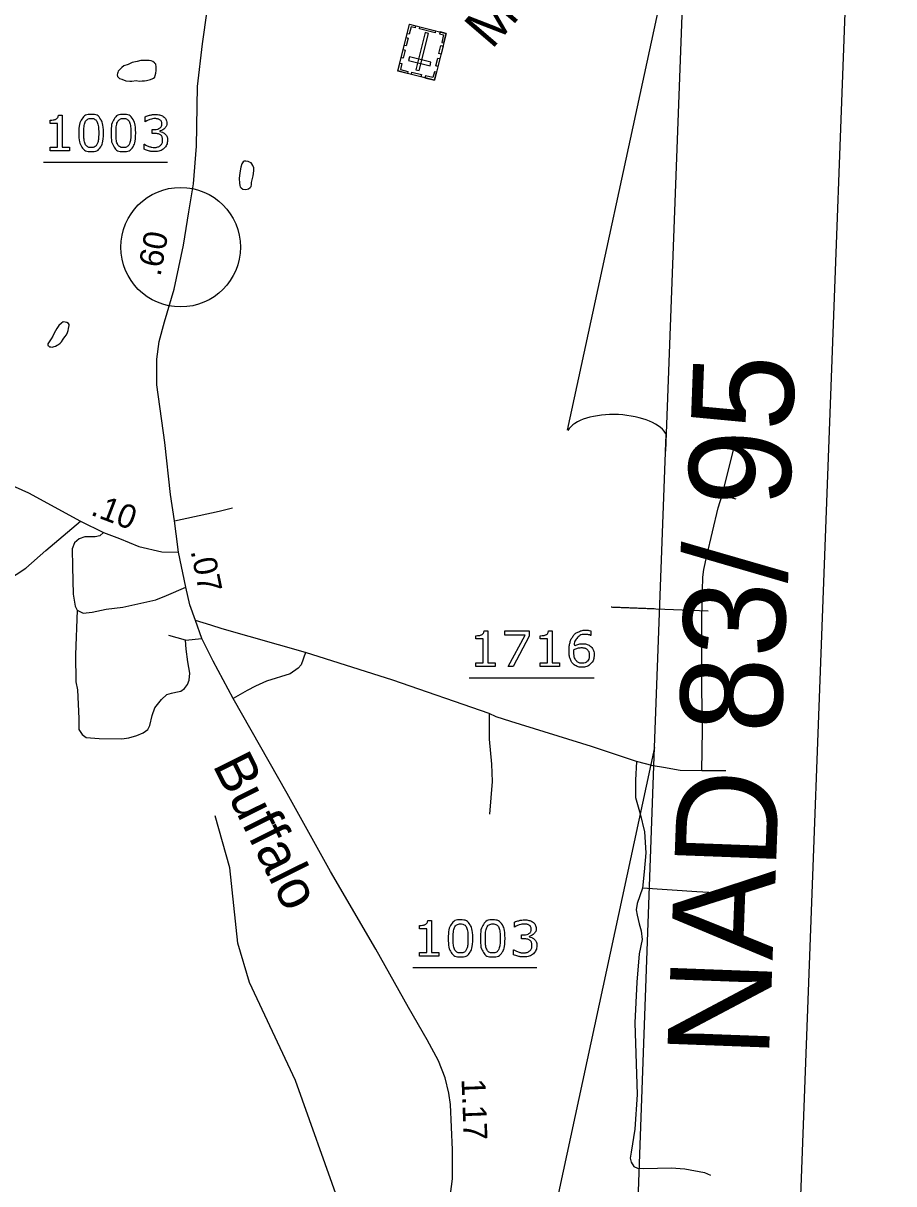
# Model space of a CAD drawing. Extents: x 2169602 to 2449496, y 721995 to 810662.
# Drawn here: x 2170470.8 to 2170579.9, y 724655.5 to 724801.1 of the extents above; entities that cross this region are included whole.
import ezdxf

# ---------------------------------------------------------------- set-up
doc = ezdxf.new("R2010")
doc.units = 0
for name, color, linetype in [('Old_Level_1', 7, 'Continuous'), ('Prop North Arrow NAD83 for Plan Sheets CELL', 7, 'Continuous'), ('Prop Shade Medium', 7, 'Continuous')]:
    doc.layers.add(name, color=color, linetype=linetype)

msp = doc.modelspace()

# ---------------------------------------------------------------- linework, layer by layer
at = {"layer": 'Old_Level_1'}
for p, q in [((2170473.29, 724783.7), (2170488.84, 724783.7)), ((2170558.41, 724741.94), (2170560.11, 724741.45)), ((2170491.09, 724723.76), (2170489, 724724.31)), ((2170491.09, 724723.76), (2170493.14, 724723.93)), ((2170526.66, 724719.02), (2170542.34, 724719.02)), ((2170519.6, 724682.67), (2170535.15, 724682.67))]:
    msp.add_line(p, q, dxfattribs=at)
for points in [[(2170008.61, 724987.87), (2170579.91, 724966.5), (2170563.13, 724517.9), (2169991.83, 724539.28)], [(2170522.32, 724793.99), (2170517.73, 724795.13), (2170519.19, 724801.01), (2170523.79, 724799.86)], [(2170519.96, 724800.82), (2170519.89, 724800.55), (2170519.39, 724800.68), (2170519.15, 724799.75), (2170518.9, 724799.81), (2170519.19, 724801.01)], [(2170519.98, 724795.29), (2170520.41, 724795.19), (2170521.57, 724799.86), (2170521.14, 724799.97)], [(2170522.39, 724799.93), (2170520.44, 724800.42), (2170520.5, 724800.68), (2170522.46, 724800.19)], [(2170523.02, 724800.05), (2170522.96, 724799.79), (2170523.46, 724799.66), (2170523.23, 724798.73), (2170523.49, 724798.66), (2170523.79, 724799.86)], [(2170519.04, 724799.27), (2170518.79, 724798.28), (2170518.53, 724798.34), (2170518.78, 724799.34)], [(2170518.66, 724797.75), (2170518.41, 724796.76), (2170518.15, 724796.82), (2170518.4, 724797.82)], [(2170521.77, 724795.79), (2170521.88, 724796.23), (2170519.17, 724796.9), (2170519.06, 724796.47)], [(2170523.39, 724798.25), (2170523.14, 724797.25), (2170522.87, 724797.32), (2170523.12, 724798.32)], [(2170517.98, 724796.13), (2170518.24, 724796.07), (2170518.06, 724795.33), (2170518.99, 724795.09), (2170518.93, 724794.84), (2170517.73, 724795.14)], [(2170523, 724796.7), (2170522.75, 724795.7), (2170522.49, 724795.77), (2170522.74, 724796.76)], [(2170520.62, 724794.42), (2170519.42, 724794.71), (2170519.49, 724794.98), (2170520.68, 724794.68)], [(2170522.57, 724794.99), (2170522.31, 724795.05), (2170522.13, 724794.31), (2170521.19, 724794.55), (2170521.13, 724794.29), (2170522.32, 724793.99)]]:
    msp.add_lwpolyline(points, close=True, dxfattribs=at)
for points in [[(2170490.24, 724734.77), (2170489.92, 724737.07), (2170489.72, 724738.72), (2170489.22, 724742.03), (2170488.49, 724748.52), (2170487.51, 724755.77), (2170487.51, 724758.97), (2170487.81, 724761.19), (2170488.45, 724763.67), (2170489.69, 724767.77), (2170490.84, 724773.27), (2170491.52, 724777.46), (2170492.12, 724781), (2170492.5, 724785.69), (2170492.59, 724793.21), (2170493.23, 724798.54), (2170493.83, 724802.68), (2170494.72, 724807.5), (2170495.36, 724811.52)], [(2170484.91, 724793.93), (2170485.29, 724793.88), (2170485.67, 724793.89), (2170485.95, 724793.89), (2170486.2, 724793.94), (2170486.71, 724794.08), (2170487, 724794.18), (2170487.1, 724794.22), (2170487.24, 724794.37), (2170487.29, 724794.56), (2170487.38, 724794.85), (2170487.42, 724795.18), (2170487.42, 724795.65), (2170487.38, 724795.99), (2170487.27, 724796.08), (2170487.23, 724796.17), (2170487, 724796.31), (2170486.8, 724796.41), (2170486.56, 724796.46), (2170486.27, 724796.46), (2170486.04, 724796.46), (2170485.52, 724796.45), (2170485.05, 724796.31), (2170484.42, 724796.21), (2170483.9, 724795.97), (2170483.39, 724795.78), (2170483.1, 724795.58), (2170482.77, 724795.25), (2170482.67, 724795.11), (2170482.63, 724794.96), (2170482.59, 724794.82), (2170482.53, 724794.67), (2170482.58, 724794.44), (2170482.72, 724794.3), (2170482.82, 724794.21), (2170483.1, 724794.11), (2170483.63, 724793.92), (2170484.11, 724793.88), (2170484.39, 724793.88), (2170484.91, 724793.93)], [(2170476.54, 724785.13), (2170474.13, 724785.13), (2170474.13, 724785.58), (2170475.05, 724785.58), (2170475.05, 724788.57), (2170474.13, 724788.57), (2170474.13, 724788.98)], [(2170475.16, 724789.6), (2170475.63, 724789.6), (2170475.63, 724785.58), (2170476.54, 724785.58), (2170476.54, 724785.13)], [(2170486.06, 724788.77), (2170486.03, 724788.77), (2170486.03, 724789.4)], [(2170487.21, 724787.3), (2170486.94, 724787.3), (2170486.94, 724787.79), (2170487.15, 724787.79)], [(2170487.87, 724787.61), (2170487.87, 724787.56)], [(2170485.91, 724785.31), (2170485.91, 724785.94), (2170485.95, 724785.94)], [(2170499.37, 724781.14), (2170499.47, 724781.47), (2170499.57, 724781.99), (2170499.66, 724782.61), (2170499.65, 724782.99), (2170499.56, 724783.27), (2170499.42, 724783.51), (2170499.32, 724783.61), (2170499.14, 724783.7), (2170498.94, 724783.8), (2170498.65, 724783.84), (2170498.46, 724783.84), (2170498.33, 724783.75), (2170498.18, 724783.51), (2170498.04, 724783.08), (2170497.9, 724782.36), (2170497.85, 724781.65), (2170497.86, 724781.08), (2170497.91, 724780.79), (2170497.95, 724780.6), (2170498.1, 724780.46), (2170498.29, 724780.32), (2170498.68, 724780.27), (2170499, 724780.37), (2170499.19, 724780.52), (2170499.34, 724780.66), (2170499.38, 724780.9), (2170499.37, 724781.14)], [(2170475.97, 724761.78), (2170476.16, 724762.06), (2170476.3, 724762.35), (2170476.39, 724762.58), (2170476.44, 724762.83), (2170476.53, 724763.2), (2170476.53, 724763.34), (2170476.44, 724763.48), (2170476.24, 724763.58), (2170476.01, 724763.63), (2170475.77, 724763.67), (2170475.54, 724763.49), (2170475.2, 724763.2), (2170474.97, 724762.82), (2170474.64, 724762.24), (2170474.45, 724761.87), (2170474.26, 724761.53), (2170473.92, 724761.05), (2170473.84, 724760.91), (2170473.83, 724760.71), (2170473.94, 724760.67), (2170474.03, 724760.53), (2170474.22, 724760.53), (2170474.37, 724760.48), (2170474.65, 724760.58), (2170474.79, 724760.63), (2170475.03, 724760.73), (2170475.17, 724760.82), (2170475.4, 724761.01), (2170475.54, 724761.15), (2170475.78, 724761.49), (2170475.97, 724761.78)], [(2170558.41, 724741.94), (2170559.94, 724748.09), (2170560.37, 724748.73), (2170560.39, 724748.75)], [(2170462.2, 724746.38), (2170471.42, 724742.24), (2170477.95, 724738.66)], [(2170555.84, 724707.33), (2170555.93, 724712.49), (2170555.84, 724717.74), (2170555.84, 724726.62), (2170555.97, 724731.66), (2170556.1, 724732.6), (2170556.48, 724734.3), (2170557.89, 724740.32), (2170558.41, 724741.94)], [(2170489.72, 724738.72), (2170495.32, 724739.94), (2170496.98, 724740.32)], [(2170464.01, 724728.17), (2170471.08, 724732.76), (2170473.59, 724735), (2170477.95, 724738.66)], [(2170477.95, 724738.66), (2170480.81, 724737.25), (2170482.81, 724736.48), (2170485.25, 724735.5), (2170488.15, 724734.81), (2170490.24, 724734.77)], [(2170480.81, 724737.25), (2170480.34, 724736.82), (2170479.78, 724736.69), (2170478.46, 724736.69), (2170477.78, 724736.44), (2170477.18, 724735.97), (2170476.88, 724735.2), (2170476.92, 724732.94), (2170477.01, 724729.52), (2170477.26, 724727.99), (2170477.52, 724727.52)], [(2170492.37, 724726.19), (2170491.65, 724728.16), (2170491.14, 724730.38), (2170490.24, 724734.77)], [(2170477.52, 724727.52), (2170478.25, 724727.13), (2170479.4, 724727.26), (2170481.15, 724727.64), (2170483.24, 724727.9), (2170487.38, 724728.8), (2170488.7, 724729.35), (2170491.14, 724730.38)], [(2170477.52, 724727.52), (2170477.31, 724721.92), (2170477.35, 724718.51), (2170477.56, 724717.49)], [(2170558.84, 724707.37), (2170555.84, 724707.33), (2170553.11, 724707.41), (2170551.02, 724707.75), (2170549.74, 724707.97), (2170547.65, 724708.52), (2170542.02, 724710.4), (2170531.89, 724713.55), (2170530.04, 724714.14), (2170529.17, 724714.54), (2170517.09, 724718.72), (2170506.16, 724722.18), (2170495.71, 724725.16), (2170494.28, 724725.61), (2170492.37, 724726.19)], [(2170524.05, 724652.05), (2170524.6, 724656.19), (2170524.56, 724659.82), (2170524.34, 724665.5), (2170524.13, 724666.91), (2170523.66, 724668.83), (2170522.81, 724670.96), (2170521.4, 724673.61), (2170519.05, 724677.66), (2170514.95, 724685), (2170509.28, 724694.74), (2170503.86, 724704.51), (2170497.07, 724716.42), (2170494.55, 724721.11), (2170493.14, 724723.93), (2170492.37, 724726.19)], [(2170529.91, 724720.45), (2170527.49, 724720.45), (2170527.49, 724720.9), (2170528.42, 724720.9), (2170528.42, 724723.89), (2170527.49, 724723.89), (2170527.49, 724724.3)], [(2170528.53, 724724.92), (2170529, 724724.92), (2170529, 724720.9), (2170529.91, 724720.9), (2170529.91, 724720.45)], [(2170534.21, 724724.24), (2170532.2, 724720.45), (2170531.55, 724720.45), (2170533.69, 724724.38), (2170531.16, 724724.38), (2170531.16, 724724.9), (2170534.21, 724724.9), (2170534.21, 724724.24)], [(2170537.98, 724720.45), (2170535.57, 724720.45), (2170535.57, 724720.9), (2170536.5, 724720.9), (2170536.5, 724723.89), (2170535.57, 724723.89), (2170535.57, 724724.3)], [(2170536.61, 724724.92), (2170537.07, 724724.92), (2170537.07, 724720.9), (2170537.98, 724720.9), (2170537.98, 724720.45)], [(2170541.91, 724724.92), (2170541.91, 724724.34), (2170541.88, 724724.34)], [(2170478.63, 724711.55), (2170480.29, 724711.42), (2170483.11, 724711.38), (2170484.01, 724711.47), (2170484.99, 724711.77), (2170485.8, 724712.11), (2170486.36, 724712.53), (2170486.61, 724713.05), (2170486.91, 724714.28), (2170487.25, 724715.27), (2170488.11, 724716.29), (2170488.75, 724716.93), (2170489.34, 724717.1), (2170489.9, 724717.23), (2170490.5, 724717.36), (2170490.97, 724717.66), (2170491.35, 724718.17), (2170491.56, 724718.72), (2170491.65, 724719.62), (2170491.39, 724721.03), (2170491.18, 724722.61), (2170491.09, 724723.76)], [(2170506.16, 724722.18), (2170505.61, 724720.64), (2170505.22, 724720.22), (2170504.24, 724719.53), (2170501.25, 724718.6), (2170499.89, 724717.96), (2170498.82, 724717.44), (2170497.07, 724716.42)], [(2170477.56, 724717.49), (2170477.73, 724713.9), (2170477.73, 724712.53), (2170478.16, 724711.89), (2170478.63, 724711.55)], [(2170529.17, 724714.54), (2170529.17, 724711.34), (2170529.47, 724708.18), (2170529.55, 724706), (2170529.21, 724701.91)], [(2170547.65, 724708.52), (2170547.52, 724706.17), (2170547.52, 724704), (2170548.12, 724701.95), (2170548.67, 724699.69), (2170548.8, 724697.08), (2170548.63, 724694.69), (2170548.42, 724692.64)], [(2170446.84, 724588.28), (2170452.46, 724595.75), (2170458.37, 724600.7), (2170460.92, 724604.08), (2170465.62, 724611.85), (2170470.9, 724624.38), (2170477.01, 724630.72), (2170481.12, 724639.06), (2170484.28, 724642.03), (2170488.41, 724644.44), (2170490.98, 724644.86), (2170502.67, 724642.98), (2170507.83, 724641.01), (2170510.8, 724642.04), (2170512.96, 724645.42), (2170512.32, 724651.13), (2170510.35, 724653.12), (2170504.91, 724668.51), (2170499.11, 724680.79), (2170497.68, 724685.73), (2170496.64, 724695.18), (2170494.83, 724701.69)], [(2170548.42, 724692.64), (2170547.73, 724690.72), (2170547.61, 724689.91), (2170547.73, 724689.23), (2170547.99, 724688.16), (2170548.25, 724687.27), (2170548.37, 724686.2), (2170547.99, 724684.41), (2170547.69, 724680.86), (2170547.44, 724675.74), (2170547.73, 724666.73), (2170547.44, 724662.42), (2170546.97, 724659.52), (2170546.84, 724658.75), (2170546.97, 724658.24), (2170547.31, 724657.73), (2170547.78, 724657.52), (2170548.55, 724657.47), (2170552, 724657.56), (2170553.71, 724657.43), (2170556.19, 724656.96), (2170556.94, 724656.62)], [(2170558.27, 724692.02), (2170555.2, 724692.17), (2170548.42, 724692.64)], [(2170522.85, 724684.1), (2170520.43, 724684.1), (2170520.43, 724684.55), (2170521.36, 724684.55), (2170521.36, 724687.54), (2170520.43, 724687.54), (2170520.43, 724687.95)], [(2170521.47, 724688.57), (2170521.94, 724688.57), (2170521.94, 724684.55), (2170522.85, 724684.55), (2170522.85, 724684.1)], [(2170532.37, 724687.74), (2170532.34, 724687.74), (2170532.34, 724688.37)], [(2170533.51, 724686.27), (2170533.24, 724686.27), (2170533.24, 724686.76), (2170533.45, 724686.76)], [(2170534.18, 724686.58), (2170534.18, 724686.53)], [(2170532.21, 724684.28), (2170532.21, 724684.91), (2170532.26, 724684.91)]]:
    msp.add_lwpolyline(points, dxfattribs=at)
for points in [[(2170480.82, 724787.36), (2170480.82, 724786.16), (2170480.45, 724785.59), (2170480.07, 724785.03), (2170479.28, 724785.03), (2170478.48, 724785.03), (2170478.11, 724785.6), (2170477.74, 724786.17), (2170477.74, 724787.35), (2170477.74, 724788.54), (2170478.12, 724789.11), (2170478.49, 724789.68), (2170479.28, 724789.68), (2170480.08, 724789.68), (2170480.45, 724789.1), (2170480.82, 724788.52), (2170480.82, 724787.36)], [(2170484.86, 724787.36), (2170484.86, 724786.16), (2170484.49, 724785.59), (2170484.11, 724785.03), (2170483.32, 724785.03), (2170482.52, 724785.03), (2170482.15, 724785.6), (2170481.78, 724786.17), (2170481.78, 724787.35), (2170481.78, 724788.54), (2170482.15, 724789.11), (2170482.53, 724789.68), (2170483.32, 724789.68), (2170484.12, 724789.68), (2170484.49, 724789.1), (2170484.86, 724788.52), (2170484.86, 724787.36)], [(2170486.03, 724789.4), (2170486.25, 724789.5), (2170486.6, 724789.59), (2170486.96, 724789.68), (2170487.29, 724789.68), (2170487.62, 724789.68), (2170487.86, 724789.62), (2170488.11, 724789.56), (2170488.31, 724789.43), (2170488.53, 724789.28), (2170488.64, 724789.08), (2170488.75, 724788.88), (2170488.75, 724788.6), (2170488.75, 724788.23), (2170488.49, 724787.95), (2170488.23, 724787.68), (2170487.87, 724787.61)], [(2170474.13, 724788.98), (2170474.31, 724788.98), (2170474.53, 724789.01), (2170474.75, 724789.04), (2170474.86, 724789.1), (2170474.99, 724789.17), (2170475.07, 724789.29), (2170475.15, 724789.4), (2170475.16, 724789.6)], [(2170480.04, 724786), (2170480.14, 724786.24), (2170480.18, 724786.57), (2170480.22, 724786.9), (2170480.22, 724787.36), (2170480.22, 724787.81), (2170480.18, 724788.15), (2170480.14, 724788.48), (2170480.03, 724788.72), (2170479.93, 724788.95), (2170479.75, 724789.07), (2170479.57, 724789.18), (2170479.28, 724789.18), (2170479, 724789.18), (2170478.82, 724789.07), (2170478.63, 724788.95), (2170478.53, 724788.71), (2170478.42, 724788.49), (2170478.39, 724788.13), (2170478.35, 724787.78), (2170478.35, 724787.35), (2170478.35, 724786.88), (2170478.38, 724786.57), (2170478.42, 724786.26), (2170478.52, 724786.01), (2170478.62, 724785.77), (2170478.8, 724785.65), (2170478.98, 724785.53), (2170479.28, 724785.53), (2170479.56, 724785.53), (2170479.75, 724785.64), (2170479.93, 724785.76), (2170480.04, 724786)], [(2170484.08, 724786), (2170484.18, 724786.24), (2170484.22, 724786.57), (2170484.25, 724786.9), (2170484.25, 724787.36), (2170484.25, 724787.81), (2170484.22, 724788.15), (2170484.18, 724788.48), (2170484.07, 724788.72), (2170483.97, 724788.95), (2170483.79, 724789.07), (2170483.61, 724789.18), (2170483.32, 724789.18), (2170483.04, 724789.18), (2170482.86, 724789.07), (2170482.67, 724788.95), (2170482.56, 724788.71), (2170482.46, 724788.49), (2170482.43, 724788.13), (2170482.39, 724787.78), (2170482.39, 724787.35), (2170482.39, 724786.88), (2170482.42, 724786.57), (2170482.45, 724786.26), (2170482.56, 724786.01), (2170482.66, 724785.77), (2170482.84, 724785.65), (2170483.02, 724785.53), (2170483.32, 724785.53), (2170483.6, 724785.53), (2170483.79, 724785.64), (2170483.97, 724785.76), (2170484.08, 724786)], [(2170487.15, 724787.79), (2170487.6, 724787.79), (2170487.87, 724787.98), (2170488.14, 724788.17), (2170488.14, 724788.54), (2170488.14, 724788.7), (2170488.07, 724788.82), (2170488.01, 724788.94), (2170487.88, 724789.02), (2170487.75, 724789.1), (2170487.61, 724789.13), (2170487.46, 724789.16), (2170487.27, 724789.16), (2170486.99, 724789.16), (2170486.67, 724789.06), (2170486.35, 724788.96), (2170486.06, 724788.77)], [(2170488.51, 724787.27), (2170488.66, 724787.14), (2170488.75, 724786.95), (2170488.84, 724786.75), (2170488.84, 724786.45), (2170488.84, 724786.14), (2170488.73, 724785.89), (2170488.62, 724785.63), (2170488.42, 724785.44), (2170488.2, 724785.23), (2170487.89, 724785.13), (2170487.59, 724785.03), (2170487.23, 724785.03), (2170486.86, 724785.03), (2170486.5, 724785.12), (2170486.14, 724785.21), (2170485.91, 724785.31)], [(2170485.95, 724785.94), (2170486.21, 724785.77), (2170486.55, 724785.66), (2170486.9, 724785.55), (2170487.22, 724785.55), (2170487.4, 724785.55), (2170487.62, 724785.61), (2170487.83, 724785.67), (2170487.96, 724785.8), (2170488.1, 724785.93), (2170488.17, 724786.09), (2170488.23, 724786.25), (2170488.23, 724786.49), (2170488.23, 724786.73), (2170488.16, 724786.89), (2170488.08, 724787.05), (2170487.95, 724787.14), (2170487.81, 724787.23), (2170487.62, 724787.26), (2170487.43, 724787.3), (2170487.21, 724787.3)], [(2170487.87, 724787.56), (2170488.01, 724787.54), (2170488.2, 724787.46), (2170488.38, 724787.39), (2170488.51, 724787.27)], [(2170527.49, 724724.3), (2170527.68, 724724.3), (2170527.9, 724724.33), (2170528.11, 724724.36), (2170528.22, 724724.42), (2170528.36, 724724.49), (2170528.44, 724724.61), (2170528.52, 724724.72), (2170528.53, 724724.92)], [(2170535.57, 724724.3), (2170535.76, 724724.3), (2170535.98, 724724.33), (2170536.19, 724724.36), (2170536.3, 724724.42), (2170536.44, 724724.49), (2170536.52, 724724.61), (2170536.6, 724724.72), (2170536.61, 724724.92)], [(2170542.34, 724721.89), (2170542.34, 724721.21), (2170541.89, 724720.78), (2170541.45, 724720.35), (2170540.8, 724720.35), (2170540.47, 724720.35), (2170540.2, 724720.45), (2170539.93, 724720.56), (2170539.72, 724720.76), (2170539.47, 724721.01), (2170539.33, 724721.42), (2170539.19, 724721.83), (2170539.19, 724722.4), (2170539.19, 724723), (2170539.32, 724723.45), (2170539.44, 724723.91), (2170539.72, 724724.27), (2170539.98, 724724.61), (2170540.4, 724724.8), (2170540.82, 724724.99), (2170541.37, 724724.99), (2170541.55, 724724.99), (2170541.67, 724724.97), (2170541.79, 724724.96), (2170541.91, 724724.92)], [(2170541.88, 724724.34), (2170541.8, 724724.39), (2170541.63, 724724.43), (2170541.46, 724724.47), (2170541.28, 724724.47), (2170540.64, 724724.47), (2170540.26, 724724.07), (2170539.87, 724723.67), (2170539.81, 724722.98), (2170540.06, 724723.13), (2170540.3, 724723.21), (2170540.55, 724723.29), (2170540.87, 724723.29), (2170541.15, 724723.29), (2170541.37, 724723.24), (2170541.59, 724723.19), (2170541.81, 724723.03), (2170542.08, 724722.85), (2170542.21, 724722.57), (2170542.34, 724722.29), (2170542.34, 724721.89)], [(2170541.73, 724721.87), (2170541.73, 724722.14), (2170541.65, 724722.33), (2170541.57, 724722.51), (2170541.38, 724722.64), (2170541.24, 724722.74), (2170541.08, 724722.77), (2170540.91, 724722.8), (2170540.73, 724722.8), (2170540.47, 724722.8), (2170540.26, 724722.74), (2170540.04, 724722.68), (2170539.81, 724722.55), (2170539.8, 724722.49), (2170539.8, 724722.43), (2170539.8, 724722.36), (2170539.8, 724722.27), (2170539.8, 724721.8), (2170539.89, 724721.53), (2170539.99, 724721.25), (2170540.16, 724721.09), (2170540.3, 724720.96), (2170540.46, 724720.9), (2170540.62, 724720.84), (2170540.81, 724720.84), (2170541.24, 724720.84), (2170541.49, 724721.1), (2170541.73, 724721.37), (2170541.73, 724721.87)], [(2170520.43, 724687.95), (2170520.62, 724687.95), (2170520.84, 724687.98), (2170521.05, 724688.01), (2170521.16, 724688.07), (2170521.3, 724688.14), (2170521.38, 724688.26), (2170521.46, 724688.37), (2170521.47, 724688.57)], [(2170527.13, 724686.33), (2170527.13, 724685.13), (2170526.76, 724684.56), (2170526.38, 724684), (2170525.59, 724684), (2170524.79, 724684), (2170524.42, 724684.57), (2170524.05, 724685.14), (2170524.05, 724686.32), (2170524.05, 724687.51), (2170524.42, 724688.08), (2170524.8, 724688.65), (2170525.59, 724688.65), (2170526.39, 724688.65), (2170526.76, 724688.07), (2170527.13, 724687.49), (2170527.13, 724686.33)], [(2170526.34, 724684.97), (2170526.45, 724685.21), (2170526.49, 724685.54), (2170526.52, 724685.87), (2170526.52, 724686.33), (2170526.52, 724686.78), (2170526.49, 724687.12), (2170526.45, 724687.45), (2170526.34, 724687.69), (2170526.24, 724687.92), (2170526.06, 724688.04), (2170525.87, 724688.15), (2170525.59, 724688.15), (2170525.31, 724688.15), (2170525.13, 724688.04), (2170524.94, 724687.92), (2170524.83, 724687.68), (2170524.73, 724687.46), (2170524.7, 724687.1), (2170524.66, 724686.75), (2170524.66, 724686.32), (2170524.66, 724685.85), (2170524.69, 724685.54), (2170524.72, 724685.23), (2170524.83, 724684.98), (2170524.93, 724684.74), (2170525.11, 724684.62), (2170525.29, 724684.5), (2170525.59, 724684.5), (2170525.87, 724684.5), (2170526.06, 724684.61), (2170526.24, 724684.73), (2170526.34, 724684.97)], [(2170531.17, 724686.33), (2170531.17, 724685.13), (2170530.79, 724684.56), (2170530.42, 724684), (2170529.63, 724684), (2170528.83, 724684), (2170528.46, 724684.57), (2170528.09, 724685.14), (2170528.09, 724686.32), (2170528.09, 724687.51), (2170528.46, 724688.08), (2170528.84, 724688.65), (2170529.63, 724688.65), (2170530.43, 724688.65), (2170530.8, 724688.07), (2170531.17, 724687.49), (2170531.17, 724686.33)], [(2170530.38, 724684.97), (2170530.49, 724685.21), (2170530.52, 724685.54), (2170530.56, 724685.87), (2170530.56, 724686.33), (2170530.56, 724686.78), (2170530.52, 724687.12), (2170530.49, 724687.45), (2170530.38, 724687.69), (2170530.28, 724687.92), (2170530.09, 724688.04), (2170529.91, 724688.15), (2170529.63, 724688.15), (2170529.35, 724688.15), (2170529.16, 724688.04), (2170528.98, 724687.92), (2170528.87, 724687.68), (2170528.77, 724687.46), (2170528.73, 724687.1), (2170528.7, 724686.75), (2170528.7, 724686.32), (2170528.7, 724685.85), (2170528.73, 724685.54), (2170528.76, 724685.23), (2170528.87, 724684.98), (2170528.97, 724684.74), (2170529.15, 724684.62), (2170529.33, 724684.5), (2170529.63, 724684.5), (2170529.91, 724684.5), (2170530.1, 724684.61), (2170530.28, 724684.73), (2170530.38, 724684.97)], [(2170532.34, 724688.37), (2170532.55, 724688.47), (2170532.91, 724688.56), (2170533.26, 724688.65), (2170533.6, 724688.65), (2170533.92, 724688.65), (2170534.17, 724688.59), (2170534.42, 724688.53), (2170534.62, 724688.4), (2170534.84, 724688.25), (2170534.95, 724688.05), (2170535.06, 724687.85), (2170535.06, 724687.57), (2170535.06, 724687.2), (2170534.8, 724686.92), (2170534.53, 724686.65), (2170534.18, 724686.58)], [(2170533.45, 724686.76), (2170533.91, 724686.76), (2170534.18, 724686.95), (2170534.45, 724687.14), (2170534.45, 724687.51), (2170534.45, 724687.67), (2170534.38, 724687.79), (2170534.31, 724687.92), (2170534.19, 724687.99), (2170534.06, 724688.07), (2170533.92, 724688.1), (2170533.77, 724688.13), (2170533.58, 724688.13), (2170533.3, 724688.13), (2170532.98, 724688.03), (2170532.66, 724687.93), (2170532.37, 724687.74)], [(2170534.82, 724686.24), (2170534.96, 724686.11), (2170535.06, 724685.92), (2170535.15, 724685.73), (2170535.15, 724685.42), (2170535.15, 724685.11), (2170535.04, 724684.86), (2170534.93, 724684.6), (2170534.73, 724684.41), (2170534.5, 724684.2), (2170534.2, 724684.1), (2170533.9, 724684), (2170533.53, 724684), (2170533.16, 724684), (2170532.8, 724684.09), (2170532.44, 724684.18), (2170532.21, 724684.28)], [(2170532.26, 724684.91), (2170532.51, 724684.74), (2170532.86, 724684.63), (2170533.2, 724684.52), (2170533.52, 724684.52), (2170533.71, 724684.52), (2170533.93, 724684.58), (2170534.14, 724684.65), (2170534.27, 724684.77), (2170534.41, 724684.9), (2170534.48, 724685.06), (2170534.54, 724685.22), (2170534.54, 724685.46), (2170534.54, 724685.7), (2170534.47, 724685.86), (2170534.39, 724686.02), (2170534.25, 724686.11), (2170534.12, 724686.2), (2170533.93, 724686.23), (2170533.74, 724686.27), (2170533.51, 724686.27)], [(2170534.18, 724686.53), (2170534.32, 724686.51), (2170534.51, 724686.43), (2170534.69, 724686.36), (2170534.82, 724686.24)]]:
    msp.add_open_spline(points, degree=3, dxfattribs=at)
at = {"layer": 'Prop North Arrow NAD83 for Plan Sheets CELL'}
for p, q in [((2170539.01, 724750.08), (2170553.91, 724819.1)), ((2170553.98, 724819.09), (2170551.3, 724747.44)), ((2170549.91, 724710.27), (2170551.38, 724749.54)), ((2170551.3, 724747.44), (2170551.38, 724749.47)), ((2170544.56, 724727.88), (2170544.49, 724727.89)), ((2170549.88, 724727.68), (2170544.56, 724727.88)), ((2170544.64, 724727.88), (2170556.63, 724727.43)), ((2170549.91, 724710.27), (2170534.74, 724639.91)), ((2170547.34, 724639.74), (2170549.91, 724710.27))]:
    msp.add_line(p, q, dxfattribs=at)
msp.add_ellipse((2170545.19, 724749.11), major_axis=(6.34, -0.28), ratio=0.461098, start_param=0.216388, end_param=2.908219, dxfattribs=at)
at = {"layer": 'Prop Shade Medium'}
msp.add_circle((2170490.49, 724773.04), 7.5, dxfattribs=at)

# ---------------------------------------------------------------- texts
at = {"layer": 'Old_Level_1'}
for s, height, rotation, p in [('Maggie', 5, 49.3335, (2170529.51, 724797.75)), ('.60', 2.971, 79.7012, (2170487.96, 724769.28)), ('.10', 2.971, 339.0442, (2170479.09, 724739.5)), ('.07', 2.971, 281.5237, (2170491.73, 724734.92)), ('Buffalo', 5, 296.5023, (2170494.45, 724708.07)), ('1.17', 2.971, 272.153, (2170525.71, 724668.69))]:
    msp.add_text(s, height=height, rotation=rotation, dxfattribs=at).set_placement(p)
at = {"layer": 'Prop North Arrow NAD83 for Plan Sheets CELL'}
msp.add_text('NAD 83/ 95', height=12.75, rotation=87.8574, dxfattribs=at).set_placement((2170564.24, 724671.24))

doc.saveas('drawing.dxf')
